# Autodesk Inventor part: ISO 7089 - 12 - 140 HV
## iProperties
Created: 2001-12
Part Number: ISO 7089 - 12 - 140 HV
Catalog Web Link: file:///F:/Cad/Autodesk/Inventor 5/Content/Iso/index.htm?doNavigateId=8E0024B3-6CA5-42D3-99D9-F0092A40B40C|74B1A93DC0A940FBB961F80085F4CFD|true
Description: Washer
Document SubType Name: Standard Catalog Part
Standard: ISO 7089 - 12 - 140 HV
Designer: Tobben
Control State: 0
Master: False
Checked Out: False
Shininess: 64.0
Length Units: 11269
Angle Units: 11279
Time Units: 11290
Mass Units: 11283
Length Display Precision: 3
Angle Display Precision: 2
Compacted: True
CLASSIFICATION: 31161807 un/spsc
MANUFACTURER: ISO Standard System
Density: 0.0
Volumn: 0.0
Area: 0.0
PropertySet Name: Model Information
Author: Tobben
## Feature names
1. Base1
